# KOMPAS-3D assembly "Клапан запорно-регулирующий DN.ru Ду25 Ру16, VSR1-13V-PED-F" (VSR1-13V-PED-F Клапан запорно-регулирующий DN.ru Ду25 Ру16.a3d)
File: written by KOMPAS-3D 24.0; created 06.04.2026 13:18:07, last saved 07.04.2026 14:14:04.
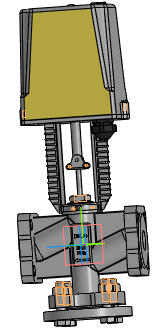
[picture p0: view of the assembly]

Document properties: Автор: R2D2; Полное имя файла: E:\Работа\Зайцев\Солянка\VSR1-13V-PED-F Клапан запорно-регулирующий DN.ru\DN25\исходные материалы\VSR1-13V-PED-F Клапан запорно-регулирующий DN.ru Ду25 Ру16.a3d

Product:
- Component [detail]: Фланец Ду25 Ру16  | qty 2  | pos. 1  | Масса: 0.888787; source file: Фланец.m3d
- Component [detail]: Фланец Ду25 Ру16  | qty 1  | pos. 2  | Масса: 0.888787; source file: Фланец.m3d
- Component [detail]: Корпус  | qty 1  | pos. 3  | Масса: 6.9; Автор: R2D2; source file: Корпус.m3d
- Component [detail]: Электропривод  | qty 1  | pos. 6  | Масса: 0.101125; Автор: R2D2; source file: Электропривод.m3d
- Component [standard]: Болт с шестигранной головкой ГОСТ Р ИСО 4014 - М12 x 50  | qty 4  | pos. 7  | Материал: Не определено (density 1000 kg/m3); Масса: 0.06029; Раздел спецификации: Стандартные изделия; Рассекать на разрезах: no; additional columns: ГОСТ Р ИСО 4014-2013
- Component [standard]: Гайка М12-6H(S18) ГОСТ 5915-70  | qty 4  | pos. 8  | Масса: 0.01567; Раздел спецификации: Стандартные изделия; Рассекать на разрезах: no; additional columns: М1,6-6H.12
- Part/product: Клапан запорно-регулирующий DN.ru Ду25 Ру16  | designation VSR1-13V-PED-F
    Масса: 7.7
    Раздел спецификации: Прочие изделия
    Примечание: D090-02888

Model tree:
1. Эскиз:1
2. Ось конической поверхности:19
3. Смещенная плоскость:19
4. ЛСК:19  (with: Плоскость XY, Плоскость ZX, Плоскость ZY, Ось X, Ось Y, Ось Z)
     Ось X. Y = -1; Ось Y. X = 1; Ось Z. Z = 1; Точка начала. Х = 30.052; Точка начала. Y = -96; Точка начала. Z = 30.052
5. Болтовое соединение
6. Массив по концентрической сетке:1  (with: Грань.Элемент выдавливания:1, Грань.Элемент вращения:1, Грань.Элемент выдавливания:2)  (4 pattern instances)
     Шаг 2 = 360; Ориентация = 2; Расстояние = 2; Расстояние = -32

Expressions: VSR1-13V-PED-F; -L/2
Referenced files in E:\Работа\Зайцев\Солянка\VSR1-13V-PED-F Клапан запорно-регулирующий DN.ru\DN25\исходные материалы\: Фланец.m3d, Корпус.m3d, Электропривод.m3d
Referenced files in C:\Program Files\ASCON\KOMPAS-3D v24\Libs\PolynomLib\DATA\vault\Methods\Kompas\3D\: PLib_Bolt_1_ISO_1100.m3d, PLib_Nut_OST92_900.m3d
Referenced files in E:\Работа\Зайцев\Солянка\VSR1-13V-PED-F Клапан запорно-регулирующий DN.ru\DN20\исходные материалы\: Фланец.m3d
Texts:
  Болт с шестигранной головкой
  Крепежное изделие ГОСТ
  Программные изделия  и базы данных
  Edge1
  Edge2
  TKR3D
  Справочник стандартных изделий
  Фланец Ду25 Ру16 (1)
  Фланец Ду25 Ру16 (2)
  Фланец Ду25 Ру16 (3)
  Болт с шестигранной головкой ГОСТ Р ИСО 4014 - М12 x 50 (1)
  hole1
  hole2
  bcut1
  hcut1
  cut1
  Плоскость XY.Начало координат
  Ось Z.Начало координат
  Плоскость ZY.Начало координат
  Плоскость ZX.Начало координат
  Ось Y.Начало координат
  Plane. Начало координат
